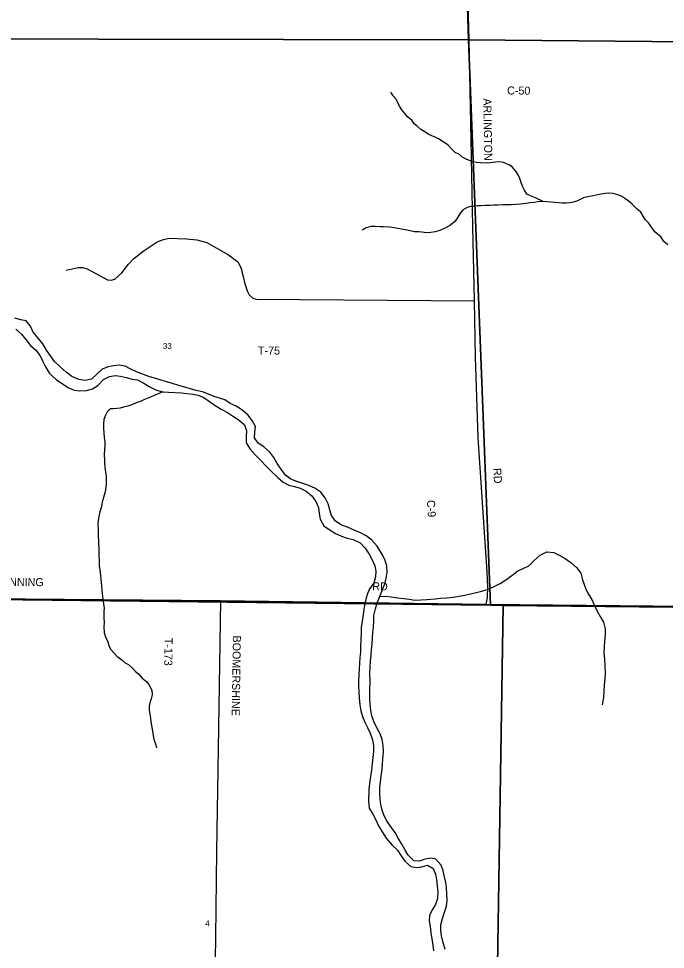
# Model space of a CAD drawing. Extents: x 1312308 to 1684953, y 460642 to 865172.
# Drawn here: x 1422870 to 1428928, y 606234 to 614954 of the extents above; entities that cross this region are included whole.
import ezdxf

# ---------------------------------------------------------------- set-up
doc = ezdxf.new("R2010")
doc.units = 0
for name, color, linetype in [('GM_X_County_Road', 7, 'Continuous'), ('GM_X_County_Road_Text', 7, 'Continuous'), ('GM_X_Major_River', 7, 'Continuous'), ('GM_X_Minor_River', 7, 'Continuous'), ('GM_X_Section', 7, 'Continuous'), ('GM_X_Section_Text', 7, 'Continuous'), ('GM_X_Township', 7, 'Continuous'), ('GM_X_Township_Road', 7, 'Continuous'), ('GM_X_Township_Road_Text', 7, 'Continuous')]:
    doc.layers.add(name, color=color, linetype=linetype)

msp = doc.modelspace()

# ---------------------------------------------------------------- linework, layer by layer
at = {"layer": 'GM_X_County_Road'}
for points in [[(1427248.1, 609464.9), (1427262.8, 609530.1), (1427265.1, 609631.9), (1427258.3, 609770.3), (1427207.4, 610514.1), (1427174.3, 611027.4), (1427149.3, 611784.7), (1427140.4, 612310.8), (1427125.7, 613004.8), (1427108.3, 613811.3), (1427096.2, 614439.7), (1427089.2, 614759.2), (1427060.1, 615869.2)], [(1427089.2, 614759.2), (1427860.7, 614750.1), (1429455.8, 614735.5), (1429745.8, 614732.5)], [(1422200.5, 609520.2), (1424759.1, 609498.2), (1427248.1, 609464.9)], [(1427248.1, 609464.9), (1427248.1, 609464.9), (1430057.8, 609437.8), (1434197.2, 609392.5)]]:
    msp.add_lwpolyline(points, dxfattribs=at)
at = {"layer": 'GM_X_Major_River'}
for points in [[(1424799.9, 611383.1), (1424752.5, 611398.8), (1424700.7, 611414), (1424649, 611435.1), (1424591.3, 611456.4), (1424533.4, 611469.7), (1424479.6, 611484.9), (1424425.8, 611502.1), (1424369.9, 611515.4), (1424310.2, 611534.7), (1424254.4, 611552), (1424196.7, 611571.3), (1424142.8, 611584.5), (1424089, 611601.7), (1423973.6, 611644.3), (1423920, 611669.5), (1423866.4, 611696.7), (1423810.5, 611708), (1423758.3, 611701.1), (1423707.9, 611692.2), (1423653.3, 611669.3), (1423551.1, 611575.3), (1423492.7, 611562.6), (1423434.8, 611571.9), (1423369.2, 611601.3), (1423313.9, 611640.6), (1423258.8, 611691.9), (1423205.7, 611741.2), (1423166.8, 611796.2), (1423131.8, 611849), (1423096.8, 611905.9), (1423053.8, 611958.9), (1423006.9, 612016.1), (1422980, 612072.8), (1422941, 612123.7), (1422889, 612132.9), (1422835.2, 612146.1)], [(1422843.1, 612043.7), (1422896.3, 611998.5), (1422937.3, 611947.4), (1422980.3, 611892.4), (1423031.5, 611847.2), (1423072.5, 611794.2), (1423097.5, 611741.5), (1423120.5, 611690.9), (1423159.3, 611630), (1423220.3, 611572.5), (1423279.6, 611531.2), (1423333, 611497.9), (1423390.6, 611472.6), (1423444.6, 611465.4), (1423504.9, 611470.1), (1423561.3, 611486.9), (1423612.1, 611517.9), (1423665.4, 611572.8), (1423722.1, 611599.7), (1423774.4, 611610.5), (1423824.4, 611605.4), (1423876.3, 611592.3), (1423932.1, 611575), (1423982.1, 611569.9), (1424037.7, 611542.7), (1424093.1, 611507.4), (1424162.5, 611471.8), (1424220.4, 611458.5), (1424272.5, 611455.4), (1424396.6, 611448.7), (1424448.6, 611441.5), (1424500.6, 611434.4), (1424552.5, 611425.2), (1424604.2, 611404), (1424710.9, 611329.6), (1424768.4, 611294.2), (1424825.9, 611262.9), (1424881.2, 611225.7), (1424934.7, 611192.4), (1424985.9, 611147.2), (1425004.8, 611092.7), (1425001.5, 611032.6), (1425000.5, 610980.5), (1425037.3, 610921.6), (1425086.4, 610868.4), (1425139.3, 610813.2), (1425188.4, 610760), (1425239.5, 610710.8), (1425296.5, 610655.4), (1425347.7, 610612.2), (1425399.2, 610583), (1425453.1, 610571.8), (1425506.9, 610554.6), (1425562.5, 610527.4), (1425615.7, 610484.1), (1425652.7, 610431.2), (1425677.6, 610374.6), (1425684.5, 610318.3), (1425695.4, 610264), (1425728.2, 610201.1), (1425779.6, 610167.9), (1425839, 610130.6), (1425892.6, 610105.3), (1425948.3, 610086.1), (1426004.2, 610072.8), (1426067.7, 610043.4), (1426116.8, 609992.2), (1426151.7, 609935.4), (1426180.7, 609882.6), (1426205.6, 609828), (1426216.6, 609777.7), (1426213.5, 609725.6), (1426198.3, 609665.8), (1426155.1, 609612.7), (1426133.9, 609559), (1426118.6, 609499.2), (1426107.4, 609439.4), (1426096, 609371.5), (1426086.6, 609305.6), (1426079.5, 609253.6), (1426078.3, 609197.5), (1426074.9, 609131.5), (1426071.8, 609075.5), (1426070.6, 609019.4), (1426065.5, 608967.4), (1426062.4, 608911.3), (1426059.3, 608861.3), (1426056.2, 608805.3), (1426053, 608747.2), (1426053.9, 608697.1), (1426054.9, 608647), (1426059.7, 608590.8), (1426064.4, 608526.6), (1426075.3, 608470.2), (1426090.2, 608415.8), (1426111.2, 608363.3)], [(1426829.6, 606362), (1426824.7, 606414.2), (1426825.7, 606464.2), (1426841, 606524), (1426860.3, 606581.7), (1426877.4, 606637.4), (1426882.7, 606695.4), (1426881.9, 606755.5), (1426879, 606809.7), (1426870, 606860), (1426859.1, 606914.3), (1426846.2, 606968.7), (1426827.3, 607023.2), (1426778.3, 607080.4), (1426726.4, 607089.5), (1426676, 607078.6), (1426625.5, 607059.7), (1426571.5, 607064.8), (1426518.5, 607118.1), (1426487.5, 607168.9), (1426460.4, 607219.5), (1426425.5, 607276.4), (1426396.5, 607329.1), (1426359.5, 607380), (1426322.5, 607432.9), (1426293.5, 607483.7), (1426274.5, 607538.2), (1426261.6, 607592.5), (1426254.7, 607642.8), (1426251.7, 607693), (1426252.8, 607749), (1426258, 607803), (1426267.1, 607856.9), (1426274.5, 607922.9), (1426279.6, 607976.9), (1426285.9, 608088.9), (1426283.1, 608145.1), (1426276.2, 608199.4), (1426255.3, 608253.9), (1426226.4, 608310.7), (1426195.5, 608367.4), (1426178.6, 608421.9), (1426169.6, 608472.2), (1426162.8, 608530.4), (1426159.9, 608586.6), (1426159.1, 608644.7), (1426161.5, 608758.9), (1426160.7, 608817), (1426161.9, 608879.1), (1426167.1, 608933.1), (1426172.3, 608991.1), (1426175.3, 609041.1), (1426180.4, 609095.1), (1426183.6, 609149.2), (1426188.7, 609205.2), (1426193.8, 609257.1), (1426197, 609313.2), (1426198, 609363.2), (1426211.3, 609425.1), (1426228.5, 609480.8), (1426251.8, 609540.4), (1426275.1, 609598), (1426300.4, 609659.6), (1426313.5, 609711.4), (1426320.7, 609767.3), (1426319.9, 609825.5), (1426302.9, 609876), (1426277.9, 609930.6), (1426227.5, 610011.9), (1426178.5, 610067), (1426125.2, 610108.3), (1426071.7, 610137.5), (1426014.1, 610162.8), (1425950.5, 610190.2), (1425894.8, 610209.5), (1425835.4, 610248.9), (1425800.4, 610299.7), (1425783.4, 610352.2), (1425768.5, 610406.7), (1425741.6, 610463.3), (1425700.6, 610518.3), (1425645.3, 610555.6), (1425579.7, 610583.1), (1425476.1, 610617.4), (1425420.4, 610638.7), (1425369.1, 610677.9), (1425328.2, 610732.9), (1425291.2, 610785.8), (1425260.3, 610842.6), (1425223.2, 610893.5), (1425168, 610940.8), (1425114.6, 610976), (1425077.6, 611026.9), (1425082.7, 611080.9), (1425089.8, 611132.9), (1425056.9, 611187.7), (1425015.9, 611242.7), (1424960.8, 611290), (1424907.3, 611323.3), (1424851.7, 611348.5), (1424799.9, 611383.1)], [(1426111.2, 608363.3), (1426136.2, 608312.6), (1426163.2, 608259.9), (1426185.9, 608197.3), (1426192.9, 608145.1), (1426193.7, 608088.9), (1426186.5, 608033), (1426181.3, 607975), (1426174, 607913.1), (1426166.8, 607853.1), (1426155.4, 607789.2), (1426150.2, 607731.2), (1426147.9, 607621.1), (1426154.6, 607556.8), (1426187.6, 607502), (1426214.5, 607447.3), (1426239.5, 607392.7), (1426274.3, 607333.8), (1426313.2, 607276.8), (1426368, 607211.5), (1426419.1, 607162.3), (1426452.2, 607111.5), (1426487.2, 607060.7), (1426544.3, 607009.3), (1426596.2, 607000.2), (1426646.5, 607007.1), (1426700.9, 607021.9), (1426752.4, 606990.8), (1426773.4, 606940.2), (1426784.4, 606887.9), (1426791.2, 606829.6), (1426796, 606773.4), (1426792.8, 606711.4), (1426773.6, 606655.7), (1426742.4, 606604.3), (1426717.3, 606552.8), (1426716.3, 606502.7), (1426723.2, 606448.4), (1426731.9, 606388.1), (1426740.8, 606333.8), (1426749.6, 606273.5), (1426756.5, 606219.3)], [(1426865.1, 606233), (1426844.6, 606307.5), (1426829.6, 606362)]]:
    msp.add_lwpolyline(points, dxfattribs=at)
at = {"layer": 'GM_X_Minor_River'}
for points in [[(1427782.3, 613240.3), (1427712.7, 613273.7), (1427663, 613292.7), (1427629.2, 613309.4), (1427607.9, 613345.9), (1427588.7, 613384.4), (1427577.3, 613418.8), (1427566, 613455.1), (1427548.7, 613491.5), (1427527.4, 613526.1), (1427494.1, 613564.8), (1427462.4, 613585.5), (1427412.7, 613606.5), (1427374.7, 613613.2), (1427338.5, 613609.9), (1427308.4, 613606.4), (1427266.1, 613601.2), (1427200, 613602.4), (1427155.9, 613607.3), (1427116, 613614), (1427062.3, 613637.1), (1427030.5, 613653.8), (1426999, 613680.5), (1426959.3, 613699.3), (1426927.8, 613730), (1426888.5, 613770.9), (1426837.1, 613805.9), (1426801.4, 613826.7), (1426771.7, 613843.3), (1426739.8, 613855.9), (1426706, 613870.6), (1426674.4, 613893.3), (1426636.7, 613914.1), (1426603.3, 613944.8), (1426573.7, 613969.4), (1426552.3, 614004), (1426512.8, 614032.8), (1426489.3, 614063.3), (1426460, 614098), (1426438.6, 614132.5), (1426425.2, 614162.9), (1426401.9, 614201.5), (1426378.5, 614232), (1426357.1, 614264.6)], [(1428949.3, 612833.1), (1428913.9, 612865.9), (1428888.6, 612906.5), (1428829.5, 612957.8), (1428771, 613039.2), (1428739.6, 613071.9), (1428718.2, 613104.4), (1428698.9, 613140.9), (1428663.4, 613169.6), (1428618.1, 613214.6), (1428578.7, 613247.5), (1428549.1, 613270.1), (1428519.3, 613286.7), (1428481.5, 613301.5), (1428439.7, 613314.3), (1428397.6, 613317.1), (1428363.5, 613315.8), (1428325.2, 613308.4), (1428295, 613303), (1428236.6, 613292), (1428202.4, 613284.6), (1428160.1, 613275.4), (1428105.4, 613248.3), (1428067, 613235), (1428036.7, 613227.5)], [(1428036.7, 613227.5), (1428002.6, 613224.1), (1427964.5, 613224.8), (1427930.4, 613227.5), (1427892.4, 613230.2), (1427856.3, 613232.9), (1427818.3, 613237.6), (1427782.3, 613240.3), (1427734.1, 613237.2), (1427699.9, 613231.8), (1427663.6, 613226.5), (1427619.4, 613221.3), (1427571.2, 613216.2), (1427527, 613213), (1427484.8, 613209.7), (1427442.7, 613210.5), (1427404.5, 613209.2), (1427356.3, 613206.1), (1427318.2, 613204.8), (1427288.1, 613203.4), (1427243.9, 613202.2), (1427197.8, 613201), (1427167.7, 613199.6), (1427135.5, 613198.2), (1427105.4, 613194.8), (1427071.1, 613185.3), (1427028.4, 613158), (1427001.7, 613126.4), (1426974.6, 613076.8), (1426947.9, 613047.2), (1426905.1, 613013.8), (1426856.4, 612986.7), (1426813.9, 612969.4), (1426771.5, 612956.1), (1426731.3, 612948.8), (1426691.1, 612947.6), (1426647.1, 612952.4), (1426617.1, 612955), (1426579, 612957.7), (1426537.1, 612966.5), (1426507.1, 612971.1), (1426457.1, 612982.1), (1426407.2, 612991), (1426351.2, 613000.1), (1426287.1, 613003.3), (1426255, 613001.9), (1426210.9, 613006.8), (1426168.8, 613005.5), (1426124.4, 612992.3), (1426087.9, 612970.9)], [(1424220.4, 611458.5), (1424088, 611402.7), (1424055.6, 611387.3), (1424017.1, 611369.9), (1423978.7, 611356.6), (1423936.2, 611339.3), (1423891.8, 611324.1), (1423851.5, 611312.8), (1423821.2, 611303.3), (1423789, 611299.9), (1423756.9, 611298.5), (1423726.8, 611299.1), (1423698.1, 611269.5), (1423683.5, 611239.7), (1423666.6, 611197.9), (1423663.7, 611155.8), (1423664.9, 611115.6), (1423668, 611071.4), (1423671.1, 611029.2), (1423676.3, 610989), (1423677.6, 610954.9), (1423674.9, 610920.8), (1423671.7, 610860.7), (1423673, 610826.5), (1423674.2, 610788.4), (1423677.4, 610750.2), (1423684.6, 610705.9), (1423689.9, 610671.7), (1423691.1, 610635.5), (1423690.5, 610601.4), (1423687.7, 610563.4), (1423678.8, 610521.4), (1423665.6, 610467.5), (1423652.7, 610423.6), (1423641.6, 610369.6), (1423630.8, 610333.7), (1423619.9, 610289.7), (1423615.2, 610255.7), (1423612.3, 610215.6), (1423613.6, 610177.5), (1423614.6, 610129.3), (1423616, 610099.2), (1423617.2, 610063), (1423618.6, 610030.9), (1423619.9, 609994.8), (1423621.2, 609962.6), (1423620.5, 609930.5), (1423623.4, 609874.3), (1423624.4, 609824.1), (1423629.8, 609793.9), (1423636.6, 609735.6), (1423640, 609705.4), (1423643.3, 609671.3), (1423644.7, 609639.1), (1423647.8, 609594.9), (1423658.1, 609510.5), (1423665.3, 609472.2), (1423670.5, 609430), (1423667.8, 609399.9), (1423669.2, 609369.8), (1423668.5, 609335.7), (1423669.7, 609295.6), (1423668.8, 609251.4), (1423671.8, 609203.2), (1423685, 609160.8), (1423704.2, 609116.3), (1423715.5, 609082), (1423730.8, 609047.6), (1423760.2, 609013), (1423793.6, 608978.2), (1423835, 608945.3), (1423868.6, 608918.7), (1423898.3, 608902), (1423933.8, 608871.3), (1423963.2, 608836.6), (1423992.9, 608816), (1424026.1, 608775.3), (1424067.6, 608742.4), (1424091, 608709.8), (1424116.1, 608663.2), (1424119.3, 608623), (1424110.4, 608581.1), (1424099.6, 608543.1), (1424091, 608513.2), (1424092.1, 608471), (1424097.4, 608436.8), (1424104.7, 608400.6), (1424108, 608366.4), (1424115.3, 608332.2), (1424125.9, 608259.8), (1424133, 608215.5), (1424142.4, 608185.2), (1424153.7, 608150.9), (1424161.2, 608120.7)], [(1426251.8, 609540.4), (1426306, 609543.2), (1426358, 609538.1), (1426418, 609528.8), (1426478, 609521.5), (1426528, 609516.4), (1426581.9, 609507.2), (1426638.1, 609507.9), (1426694.3, 609510.7), (1426770.7, 609519.1), (1426822.9, 609523.9), (1426879.1, 609526.7), (1426943.4, 609535.3), (1426993.7, 609544.3), (1427048, 609553.1), (1427102.4, 609563.9), (1427156.8, 609576.8), (1427207.2, 609589.7), (1427267.7, 609608.4), (1427324.4, 609633.2), (1427381.1, 609662), (1427431.9, 609695), (1427490.9, 609737.8), (1427546, 609780.7), (1427596.5, 609801.6), (1427647.2, 609826.6), (1427698.3, 609877.5), (1427753.5, 609928.4), (1427816.3, 609957.1), (1427882.3, 609951.7), (1427934, 609928.5), (1427989.5, 609897.2), (1428042.8, 609860), (1428095.9, 609810.8), (1428136.9, 609757.8), (1428151.7, 609697.3), (1428178.2, 609618.6), (1428205.1, 609563.9), (1428238.1, 609511.1), (1428265, 609456.4), (1428288, 609401.8), (1428317, 609351.1), (1428348, 609298.3), (1428364.8, 609237.8), (1428363.5, 609177.7), (1428358.3, 609119.8), (1428353.2, 609067.8), (1428350, 609007.7), (1428356.9, 608953.5), (1428361.6, 608889.2), (1428362.2, 608823.1), (1428361, 608765), (1428353.8, 608709.1), (1428352.6, 608651), (1428347.4, 608595), (1428338.4, 608543.1), (1428336, 608525.1)]]:
    msp.add_lwpolyline(points, dxfattribs=at)
at = {"layer": 'GM_X_Section'}
for points in [[(1421948.9, 619535.5), (1426939.4, 619468.3), (1427084.1, 614755.3), (1421880.4, 614765)], [(1426939.4, 619468.3), (1432643.4, 619381.8), (1432580.9, 614705.3), (1427084.1, 614755.3)], [(1427084.1, 614755.3), (1427288.4, 609459), (1422083.8, 609518.6), (1421912, 609528.3), (1421880.4, 614765)], [(1432580.9, 614705.3), (1432499.1, 609405.2), (1427408.4, 609456.4), (1427288.4, 609459), (1427084.1, 614755.3)], [(1422083.8, 609518.6), (1427288.4, 609459), (1427408.4, 609456.4), (1427318.8, 603698.4), (1421984.3, 603858.8)], [(1427408.4, 609456.4), (1432499.1, 609405.2), (1432761, 609399.6), (1432672, 603575.6), (1427318.8, 603698.4)]]:
    msp.add_lwpolyline(points, close=True, dxfattribs=at)
at = {"layer": 'GM_X_Township'}
for points in [[(1443487.4, 629689.1), (1443383.2, 625252.4), (1443279.1, 619936.6), (1443262.6, 619245.4), (1443164.3, 614625), (1443062.5, 609310), (1440472, 609335.1), (1437771.4, 609361.5), (1435199.7, 609380.4), (1434197.2, 609392.5), (1430057.8, 609437.8), (1427248.1, 609464.9), (1424759.1, 609498.2), (1422200.5, 609520.2), (1411036.3, 609617.7), (1410999.4, 609618.2), (1411017.8, 611981.1), (1411020.1, 612268.6), (1411090.2, 617032.9), (1411094.7, 617623.7), (1411153.4, 624951), (1411163.3, 625647.7), (1411180.4, 628296.4), (1411210.5, 633565.2)], [(1410955.4, 603991.6), (1410977, 606750.9), (1410982, 607392.1), (1410997.9, 609428.6), (1410999.4, 609618.2), (1411036.3, 609617.7), (1422200.5, 609520.2), (1424759.1, 609498.2), (1427248.1, 609464.9), (1430057.8, 609437.8), (1434197.2, 609392.5), (1435199.7, 609380.4), (1437771.4, 609361.5), (1440472, 609335.1), (1443062.5, 609310), (1445748.3, 609283.3), (1452218.2, 609194.8), (1453828.1, 609169), (1453803.6, 608986.7), (1453761.5, 603813.9)]]:
    msp.add_lwpolyline(points, dxfattribs=at)
at = {"layer": 'GM_X_Township_Road'}
for points in [[(1423314.7, 612597.7), (1423428, 612622.9), (1423470, 612623.7), (1423512.7, 612608.6), (1423703.2, 612506.3), (1423737.5, 612504.6), (1423769.4, 612512.2), (1423836.6, 612570.9), (1423898.6, 612652.3), (1423944.8, 612704.3), (1424047.1, 612780.7), (1424167.9, 612862.8), (1424227.5, 612885.5), (1424277, 612896.4), (1424442.2, 612892.2), (1424540.4, 612880.4), (1424631.8, 612856.1), (1424742.6, 612794.9), (1424834.8, 612741.2), (1424922.9, 612674.1), (1424952.5, 612621.1), (1424972.4, 612537.3), (1424986.7, 612482.8), (1425011, 612404.8), (1425027.8, 612366.2), (1425064.7, 612333.5), (1425095.7, 612324.2), (1427140.4, 612310.8)], [(1424759.1, 609498.2), (1424739.4, 608111.7), (1424723.8, 607153.7), (1424713.5, 606348.3)], [(1424713.5, 606348.3), (1424710.8, 606136.3), (1424689.9, 604458.4)]]:
    msp.add_lwpolyline(points, dxfattribs=at)

# ---------------------------------------------------------------- texts
at = {"layer": 'GM_X_County_Road_Text'}
for s, rotation, p in [('C-50', 359.31423, (1427445.1, 614243.7)), ('ARLINGTON', 271.06123, (1427221.8, 614206.8)), ('RD', 273.91164, (1427314, 610740.9)), ('C-9', 273.66168, (1426693.6, 610441.6)), ('MANNING', 359.28902, (1422630.5, 609642.5)), ('RD', 359.01279, (1426181.8, 609598.4))]:
    msp.add_text(s, height=75, rotation=rotation, dxfattribs=at).set_placement(p)
at = {"layer": 'GM_X_Section_Text'}
for s, height, p in [('33', 55.25, (1424221.8, 611859)), ('4', 55.3, (1424617.8, 606450.8))]:
    msp.add_text(s, height=height, rotation=0.00001, dxfattribs=at).set_placement(p)
at = {"layer": 'GM_X_Township_Road_Text'}
for s, rotation, p in [('T-75', 359.64652, (1425111.8, 611807.2)), ('T-173', 269.15792, (1424237.9, 609153.7)), ('BOOMERSHINE', 269.14488, (1424876.6, 609174.6))]:
    msp.add_text(s, height=75, rotation=rotation, dxfattribs=at).set_placement(p)

doc.saveas('drawing.dxf')
